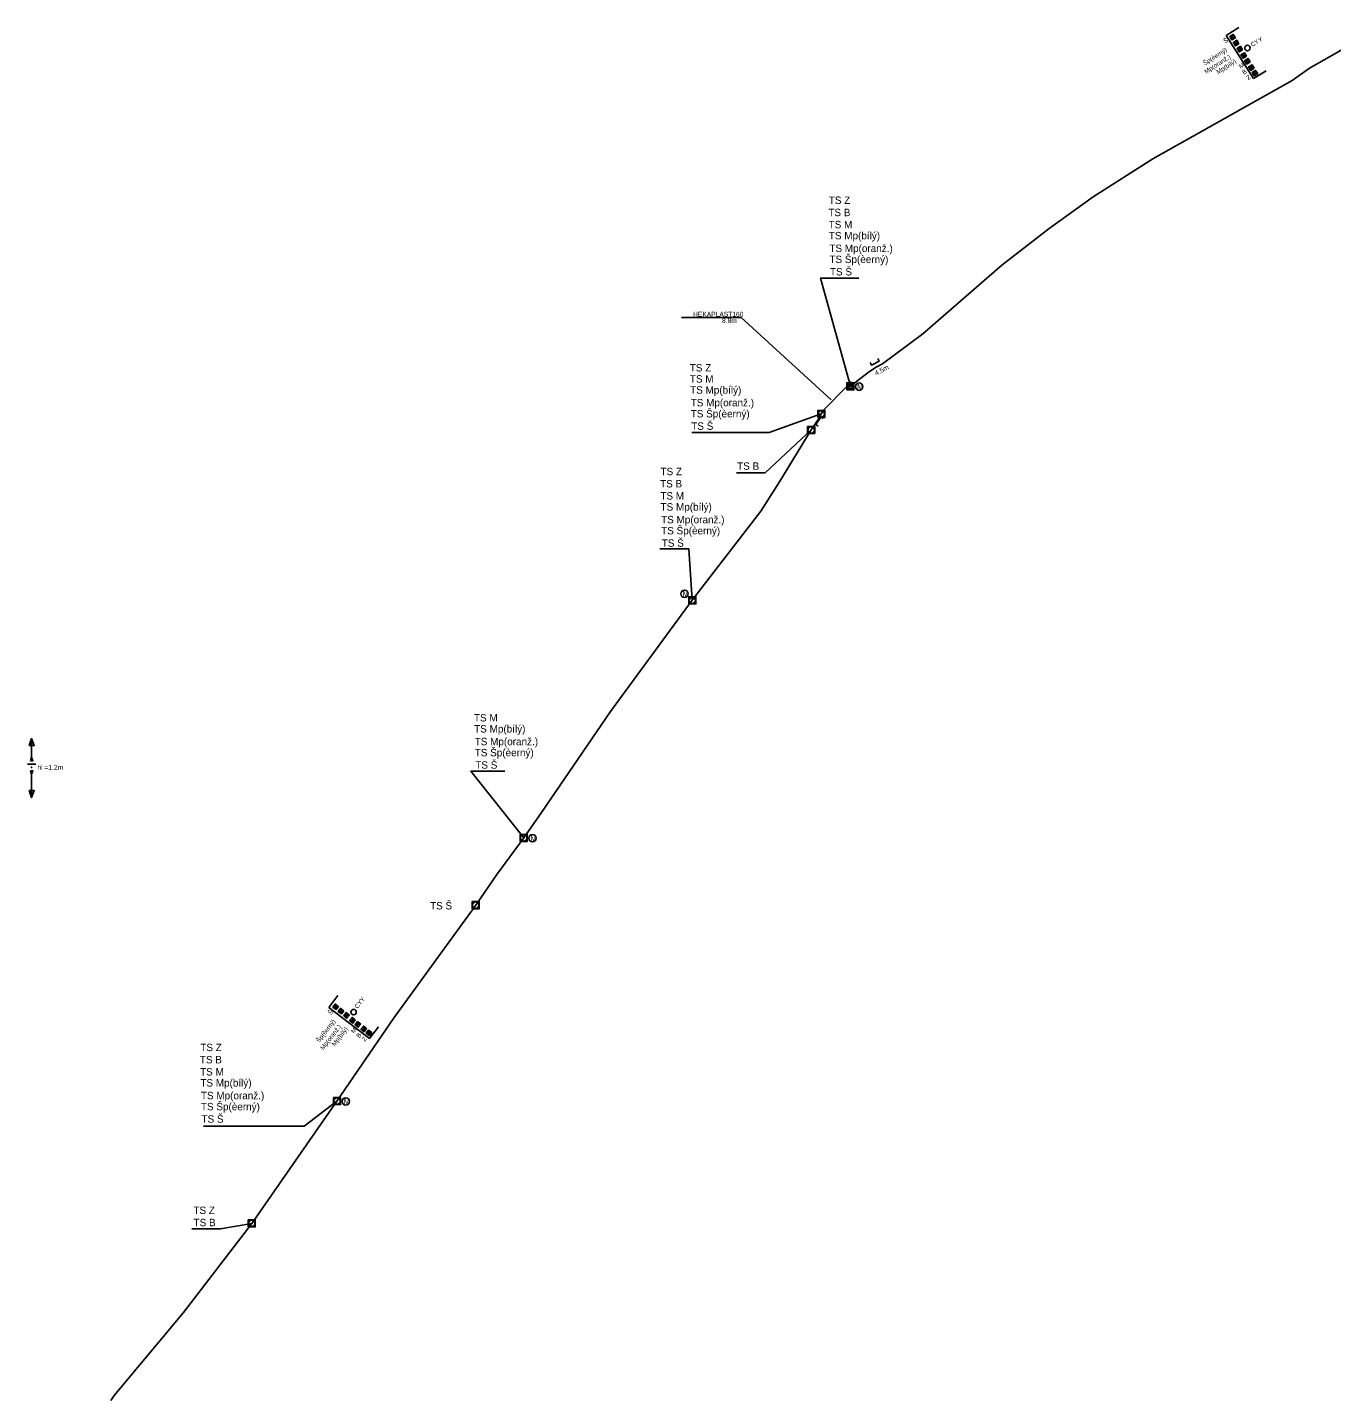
# Model space of a CAD drawing. Extents: x -566419 to -564928, y -1204142 to -1203285.
# Drawn here: x -566419.5 to -566067.8, y -1204141.6 to -1203771.3 of the extents above; entities that cross this region are included whole.
import ezdxf

# ---------------------------------------------------------------- set-up
doc = ezdxf.new("R2010")
doc.units = 0
for name, color, linetype in [('Trasa DialT', 7, 'Continuous'), ('Vrstva 10', 7, 'Continuous'), ('Vrstva 13', 7, 'Continuous'), ('Vrstva 14', 7, 'Continuous'), ('Vrstva 4', 7, 'Continuous'), ('Vrstva 58', 7, 'Continuous'), ('Vrstva 59', 7, 'Continuous'), ('Vrstva 61', 7, 'Continuous')]:
    doc.layers.add(name, color=color, linetype=linetype)

msp = doc.modelspace()

# ---------------------------------------------------------------- linework, layer by layer
at = {"layer": 'Trasa DialT'}
msp.add_lwpolyline([(-566397.02, -1204141.58), (-566396.11, -1204140.22), (-566377.44, -1204117.86), (-566359, -1204093.8), (-566336.01, -1204060.82), (-566320.6, -1204038.3), (-566298.59, -1204007.98), (-566292.89, -1203999.72), (-566285.64, -1203989.84), (-566280.88, -1203982.95), (-566262.26, -1203955.75), (-566240.17, -1203925.76), (-566221.66, -1203901.71), (-566216.62, -1203893.81), (-566208.1, -1203879.81), (-566206.96, -1203878.09), (-566205.79, -1203876.34), (-566205.38, -1203875.49), (-566204.75, -1203874.47), (-566198.62, -1203868.15), (-566197.54, -1203868.05), (-566192.72, -1203864.34), (-566190.72, -1203862.99), (-566188.84, -1203861.99), (-566178.02, -1203853.91), (-566156.67, -1203835.36), (-566143.93, -1203825.51), (-566132.02, -1203816.96), (-566115.98, -1203806.65), (-566078.42, -1203785.6), (-566073.67, -1203782.22), (-566056.63, -1203772.53)], dxfattribs=at)
at = {"layer": 'Vrstva 10'}
for p, q in [((-566096.18, -1203773.4), (-566092.8, -1203771.26)), ((-566094.61, -1203774.64), (-566094.27, -1203773.14)), ((-566088.8, -1203785.06), (-566096.18, -1203773.4)), ((-566093.69, -1203774.06), (-566095.19, -1203773.72)), ((-566092.73, -1203775.65), (-566094.23, -1203775.31)), ((-566093.65, -1203776.23), (-566093.31, -1203774.73)), ((-566091.75, -1203777.26), (-566093.26, -1203776.92)), ((-566092.67, -1203777.84), (-566092.33, -1203776.34)), ((-566090.69, -1203779.01), (-566092.2, -1203778.67)), ((-566091.61, -1203779.59), (-566091.28, -1203778.08)), ((-566089.7, -1203780.57), (-566091.21, -1203780.23)), ((-566090.62, -1203781.15), (-566090.28, -1203779.65)), ((-566088.63, -1203782.26), (-566090.13, -1203781.92)), ((-566089.55, -1203782.84), (-566089.21, -1203781.34)), ((-566087.68, -1203783.76), (-566089.18, -1203783.43)), ((-566085.42, -1203782.93), (-566088.8, -1203785.06)), ((-566088.6, -1203784.35), (-566088.26, -1203782.84)), ((-566338.2, -1204035.54), (-566335.76, -1204032.38)), ((-566327.27, -1204043.97), (-566338.2, -1204035.54)), ((-566335.57, -1204035.28), (-566337.1, -1204035.48)), ((-566336.24, -1204036.14), (-566336.44, -1204034.61)), ((-566334.8, -1204037.3), (-566334.99, -1204035.78)), ((-566334.13, -1204036.44), (-566335.66, -1204036.64)), ((-566332.66, -1204037.62), (-566334.19, -1204037.82)), ((-566333.32, -1204038.48), (-566333.52, -1204036.96)), ((-566331.06, -1204038.9), (-566332.59, -1204039.1)), ((-566331.73, -1204039.76), (-566331.93, -1204038.23)), ((-566330.26, -1204040.89), (-566330.46, -1204039.36)), ((-566329.6, -1204040.03), (-566331.13, -1204040.22)), ((-566328.01, -1204041.25), (-566329.54, -1204041.45)), ((-566328.68, -1204042.11), (-566328.88, -1204040.58)), ((-566326.6, -1204042.33), (-566328.13, -1204042.53)), ((-566327.27, -1204043.2), (-566327.47, -1204041.67)), ((-566324.83, -1204040.8), (-566327.27, -1204043.97))]:
    msp.add_line(p, q, dxfattribs=at)
for points in [[(-566093.69, -1203774.06), (-566094.27, -1203773.14), (-566095.19, -1203773.72), (-566094.61, -1203774.64)], [(-566092.73, -1203775.65), (-566093.31, -1203774.73), (-566094.23, -1203775.31), (-566093.65, -1203776.23)], [(-566091.75, -1203777.26), (-566092.33, -1203776.34), (-566093.26, -1203776.92), (-566092.67, -1203777.84)], [(-566090.69, -1203779.01), (-566091.28, -1203778.08), (-566092.2, -1203778.67), (-566091.61, -1203779.59)], [(-566089.7, -1203780.57), (-566090.28, -1203779.65), (-566091.21, -1203780.23), (-566090.62, -1203781.15)], [(-566088.63, -1203782.26), (-566089.21, -1203781.34), (-566090.13, -1203781.92), (-566089.55, -1203782.84)], [(-566087.68, -1203783.76), (-566088.26, -1203782.84), (-566089.18, -1203783.43), (-566088.6, -1203784.35)], [(-566335.57, -1204035.28), (-566336.44, -1204034.61), (-566337.1, -1204035.48), (-566336.24, -1204036.14)], [(-566334.13, -1204036.44), (-566334.99, -1204035.78), (-566335.66, -1204036.64), (-566334.8, -1204037.3)], [(-566332.66, -1204037.62), (-566333.52, -1204036.96), (-566334.19, -1204037.82), (-566333.32, -1204038.48)], [(-566331.06, -1204038.9), (-566331.93, -1204038.23), (-566332.59, -1204039.1), (-566331.73, -1204039.76)], [(-566329.6, -1204040.03), (-566330.46, -1204039.36), (-566331.13, -1204040.22), (-566330.26, -1204040.89)], [(-566328.01, -1204041.25), (-566328.88, -1204040.58), (-566329.54, -1204041.45), (-566328.68, -1204042.11)], [(-566326.6, -1204042.33), (-566327.47, -1204041.67), (-566328.13, -1204042.53), (-566327.27, -1204043.2)]]:
    msp.add_lwpolyline(points, close=True, dxfattribs=at)
for centre in [(-566090.44, -1203776.8), (-566331.52, -1204036.83)]:
    msp.add_circle(centre, 0.726, dxfattribs=at)
at = {"layer": 'Vrstva 13'}
for points in [[(-566192.72, -1203864.34), (-566190.72, -1203862.99), (-566188.84, -1203861.99)], [(-566204.75, -1203874.47), (-566198.62, -1203868.15)], [(-566206.96, -1203878.09), (-566205.79, -1203876.34)]]:
    msp.add_lwpolyline(points, dxfattribs=at)
at = {"layer": 'Vrstva 14'}
for points in [[(-566195.26, -1203838.84), (-566205.57, -1203838.84), (-566197.54, -1203868.05)], [(-566205.38, -1203875.49), (-566219.45, -1203880.53), (-566240.34, -1203880.53)], [(-566208.1, -1203879.81), (-566220.52, -1203891.35), (-566228.29, -1203891.35)], [(-566240.17, -1203925.76), (-566241.07, -1203911.9), (-566248.97, -1203911.9)], [(-566290.76, -1203971.8), (-566299.87, -1203971.8), (-566285.64, -1203989.84)], [(-566336.01, -1204060.82), (-566344.84, -1204067.56), (-566372.05, -1204067.56)], [(-566359, -1204093.8), (-566367.43, -1204095.23), (-566375.12, -1204095.23)]]:
    msp.add_lwpolyline(points, dxfattribs=at)
for points in [[(-566198.5, -1203869.01), (-566196.58, -1203869.01), (-566196.58, -1203867.09), (-566198.5, -1203867.09)], [(-566206.34, -1203876.45), (-566204.42, -1203876.45), (-566204.42, -1203874.53), (-566206.34, -1203874.53)], [(-566209.06, -1203880.77), (-566207.14, -1203880.77), (-566207.14, -1203878.85), (-566209.06, -1203878.85)], [(-566241.13, -1203926.72), (-566239.21, -1203926.72), (-566239.21, -1203924.8), (-566241.13, -1203924.8)], [(-566286.6, -1203990.8), (-566284.68, -1203990.8), (-566284.68, -1203988.88), (-566286.6, -1203988.88)], [(-566299.55, -1204008.94), (-566297.63, -1204008.94), (-566297.63, -1204007.02), (-566299.55, -1204007.02)], [(-566336.97, -1204061.78), (-566335.05, -1204061.78), (-566335.05, -1204059.86), (-566336.97, -1204059.86)], [(-566359.96, -1204094.76), (-566358.04, -1204094.76), (-566358.04, -1204092.84), (-566359.96, -1204092.84)]]:
    msp.add_lwpolyline(points, close=True, dxfattribs=at)
for centre in [(-566197.54, -1203868.05), (-566205.38, -1203875.49), (-566208.1, -1203879.81), (-566240.17, -1203925.76), (-566285.64, -1203989.84), (-566298.59, -1204007.98), (-566336.01, -1204060.82), (-566359, -1204093.8)]:
    msp.add_circle(centre, 0.864, dxfattribs=at)
at = {"layer": 'Vrstva 4'}
msp.add_lwpolyline([(-566198.04, -1203867.55), (-566197.04, -1203867.55), (-566197.04, -1203868.55), (-566198.04, -1203868.55)], close=True, dxfattribs=at)
msp.add_lwpolyline([(-566197.41, -1203867.55), (-566197.41, -1203866.92), (-566197.67, -1203866.92), (-566197.67, -1203867.55)], dxfattribs=at)
at = {"layer": 'Vrstva 58'}
for p, q in [((-566418.36, -1203969.04), (-566418.36, -1203963.04)), ((-566419.49, -1203969.97), (-566417.24, -1203969.97)), ((-566418.36, -1203978.97), (-566418.36, -1203971.74))]:
    msp.add_line(p, q, dxfattribs=at)
for points in [[(-566419.05, -1203964.92), (-566418.36, -1203963.04), (-566417.68, -1203964.92)], [(-566418.71, -1203969.04), (-566418.36, -1203968.1), (-566418.02, -1203969.04)], [(-566418.71, -1203971.74), (-566418.02, -1203971.74), (-566418.36, -1203972.68)], [(-566419.05, -1203977.09), (-566418.36, -1203978.97), (-566417.68, -1203977.09)]]:
    msp.add_lwpolyline(points, close=True, dxfattribs=at)
msp.add_circle((-566418.37, -1203970.81), 0.075, dxfattribs=at)
at = {"layer": 'Vrstva 59'}
for points in [[(-566192.24, -1203861.61), (-566191.88, -1203862.33), (-566189.73, -1203861.23), (-566190.1, -1203860.52)], [(-566204.88, -1203876.77), (-566205.54, -1203876.33), (-566206.88, -1203878.32), (-566206.21, -1203878.77)]]:
    msp.add_lwpolyline(points, dxfattribs=at)
for centre in [(-566195.17, -1203868.14), (-566242.26, -1203924.02), (-566283.27, -1203989.93), (-566333.64, -1204060.91)]:
    msp.add_circle(centre, 1, dxfattribs=at)
at = {"layer": 'Vrstva 61'}
for p, q in [((-566226.95, -1203849.45), (-566243.1, -1203849.45)), ((-566202.71, -1203871.65), (-566226.95, -1203849.45))]:
    msp.add_line(p, q, dxfattribs=at)

# ---------------------------------------------------------------- texts
at = {"layer": 'Vrstva 10'}
for s, rotation, p in [('Šp(èerný)', 32.3288, (-566101.94, -1203781.52)), ('Š', 32.3288, (-566096.45, -1203775.63)), ('CYY', 32.3288, (-566089.11, -1203776.56)), ('Mp(oranž.)', 32.3288, (-566101.6, -1203783.79)), ('Mp(bílý)', 32.3288, (-566098.36, -1203783.91)), ('M', 32.3288, (-566092.32, -1203782.41)), ('B', 32.3288, (-566091.39, -1203784.05)), ('Z', 32.3288, (-566090.29, -1203785.51)), ('Š', 52.3776, (-566337.63, -1204037.7)), ('CYY', 52.3776, (-566330.45, -1204036.01)), ('Šp(èerný)', 52.3776, (-566340.76, -1204045.11)), ('Mp(oranž.)', 52.3776, (-566339.67, -1204047.13)), ('Mp(bílý)', 52.3776, (-566336.59, -1204046.13)), ('M', 52.3776, (-566331.43, -1204042.66)), ('B', 52.3776, (-566329.98, -1204043.88)), ('Z', 52.3776, (-566328.46, -1204044.86))]:
    msp.add_text(s, height=1.2, rotation=rotation, dxfattribs=at).set_placement(p)
at = {"layer": 'Vrstva 14'}
for s, p in [('TS Z', (-566203.36, -1203818.86)), ('TS B', (-566203.48, -1203822.16)), ('TS M', (-566203.4, -1203825.42)), ('TS Mp(bílý)', (-566203.34, -1203828.4)), ('TS Mp(oranž.)', (-566203.2, -1203831.83)), ('TS Šp(èerný)', (-566203.19, -1203834.81)), ('TS Š', (-566203.04, -1203838.15)), ('TS Z', (-566240.85, -1203864.05)), ('TS M', (-566240.82, -1203867.05)), ('TS Mp(bílý)', (-566240.76, -1203870.03)), ('TS Mp(oranž.)', (-566240.61, -1203873.46)), ('TS Šp(èerný)', (-566240.6, -1203876.44)), ('TS Š', (-566240.45, -1203879.78)), ('TS Z', (-566248.74, -1203892.02)), ('TS B', (-566228.08, -1203890.56)), ('TS B', (-566248.86, -1203895.32)), ('TS M', (-566248.79, -1203898.59)), ('TS Mp(bílý)', (-566248.73, -1203901.56)), ('TS Mp(oranž.)', (-566248.58, -1203904.99)), ('TS Šp(èerný)', (-566248.57, -1203907.98)), ('TS Š', (-566248.42, -1203911.32)), ('TS M', (-566299.06, -1203958.44)), ('TS Mp(bílý)', (-566299, -1203961.42)), ('TS Mp(oranž.)', (-566298.86, -1203964.85)), ('TS Šp(èerný)', (-566298.85, -1203967.83)), ('TS Š', (-566298.7, -1203971.17)), ('TS Š', (-566310.9, -1204009.13)), ('TS Z', (-566372.87, -1204047.35)), ('TS B', (-566372.98, -1204050.65)), ('TS M', (-566372.91, -1204053.92)), ('TS Mp(bílý)', (-566372.85, -1204056.89)), ('TS Mp(oranž.)', (-566372.7, -1204060.32)), ('TS Šp(èerný)', (-566372.7, -1204063.31)), ('TS Š', (-566372.54, -1204066.65)), ('TS Z', (-566374.73, -1204091.27)), ('TS B', (-566374.68, -1204094.57))]:
    msp.add_text(s, height=2, dxfattribs=at).set_placement(p)
at = {"layer": 'Vrstva 59'}
for p in [(-566195.73, -1203868.89), (-566242.81, -1203924.77), (-566283.83, -1203990.68), (-566334.2, -1204061.66)]:
    msp.add_text('M', height=1.5, dxfattribs=at).set_placement(p)
at = {"layer": 'Vrstva 61'}
for s, p in [('HEKAPLAST160', (-566239.95, -1203849.25)), ('8.8m', (-566232.15, -1203850.95)), ('hl.=1.2m', (-566416.81, -1203971.44))]:
    msp.add_text(s, height=1.3, dxfattribs=at).set_placement(p)
msp.add_text('4.5m', height=1.3, rotation=28.0092, dxfattribs=at).set_placement((-566190.56, -1203865.17))

doc.saveas('drawing.dxf')
